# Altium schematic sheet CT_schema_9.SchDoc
size 391 x 278 mm
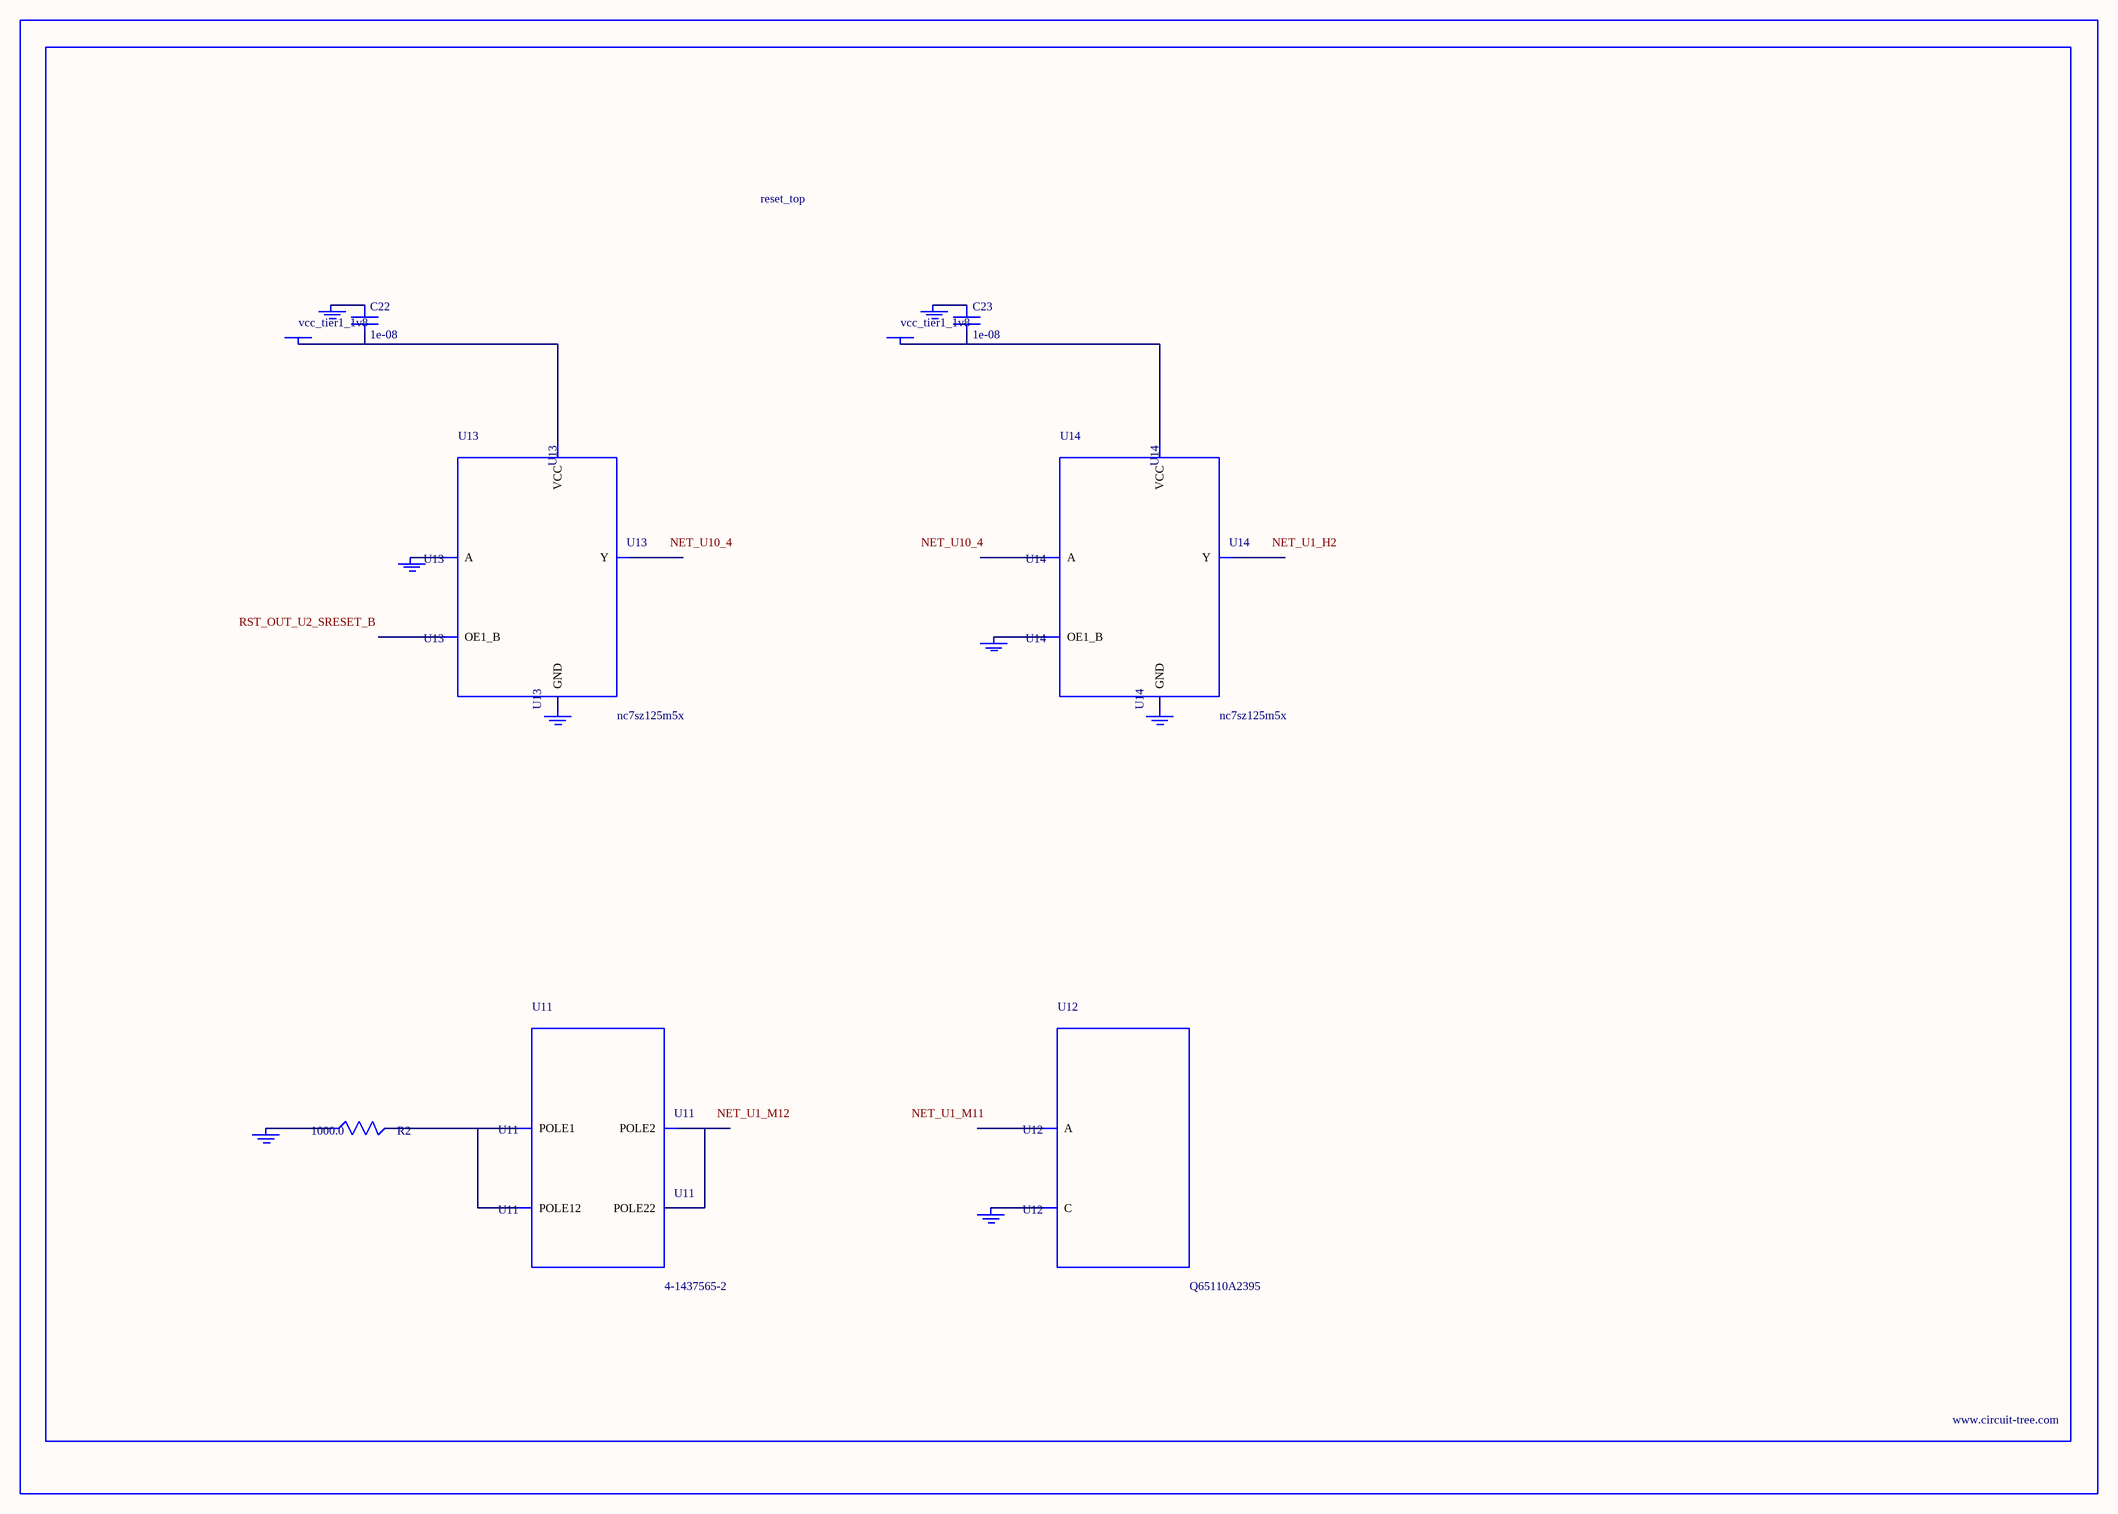
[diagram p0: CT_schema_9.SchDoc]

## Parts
BORDER8  (no value)
C22  1e-08  [C0402]
C23  1e-08  [C0402]
GND_INSTANCE_8_0  (no value)
GND_INSTANCE_8_1  (no value)
GND_INSTANCE_8_2  (no value)
GND_INSTANCE_8_3  (no value)
GND_INSTANCE_8_4  (no value)
GND_INSTANCE_8_5  (no value)
GND_INSTANCE_8_6  (no value)
GND_INSTANCE_8_7  (no value)
POWER_INSTANCE_8_0  vcc_tier1_1v8
POWER_INSTANCE_8_1  vcc_tier1_1v8
R2  1000.0  [R0603]
U11  4-1437565-2  [SW_4-1437565-2]
U12  Q65110A2395  [LGM67K-G1J2-24-Z]
U13  nc7sz125m5x  [NC7SZ125M5X]
U14  nc7sz125m5x  [NC7SZ125M5X]

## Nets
NetC22_1: C22.1 GND_INSTANCE_8_2.0(GND)
NetC22_2: C22.2 POWER_INSTANCE_8_0.0(PWR) U13.5(VCC)
NetC23_1: C23.1 GND_INSTANCE_8_5.0(GND)
NetC23_2: C23.2 POWER_INSTANCE_8_1.0(PWR) U14.5(VCC)
NetGND_INSTANCE_8_0_0: GND_INSTANCE_8_0.0(GND) R2.1
NetGND_INSTANCE_8_1_0: GND_INSTANCE_8_1.0(GND) U12.C
NetGND_INSTANCE_8_3_0: GND_INSTANCE_8_3.0(GND) U13.2(A)
NetGND_INSTANCE_8_4_0: GND_INSTANCE_8_4.0(GND) U13.3(GND)
NetGND_INSTANCE_8_6_0: GND_INSTANCE_8_6.0(GND) U14.1(OE1_B)
NetGND_INSTANCE_8_7_0: GND_INSTANCE_8_7.0(GND) U14.3(GND)
NetR2_2: R2.2 U11.1(POLE1) U11.2(POLE12)
NetU11_3: U11.3(POLE2) U11.4(POLE22)

Not connected (* = marked no-connect by the designer): U12 A; U13 1(OE1_B) 4(Y); U14 2(A) 4(Y)

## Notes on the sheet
- Labels drawn without touching a wire or pin: NET_U1_H2, NET_U1_M11, NET_U1_M12, NET_U10_4, RST_OUT_U2_SRESET_B

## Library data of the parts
BORDER8 = BORDER_PAGE8
C22 C23 = C0402C103K3RAC
GND_INSTANCE_8_0-GND_INSTANCE_8_7 = GND
POWER_INSTANCE_8_0 POWER_INSTANCE_8_1 = PWR
R2 = RC0603JR-071KL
